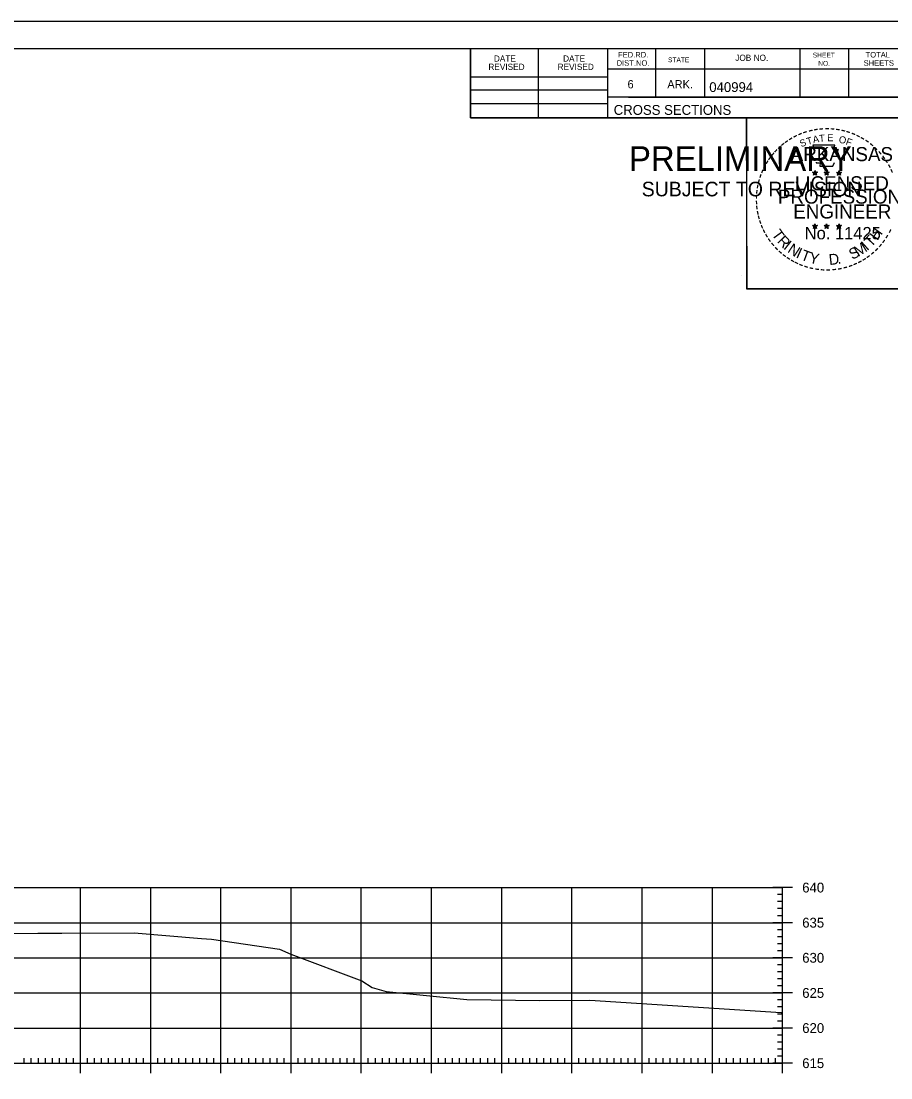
# Model space of a CAD drawing. Extents: x 1381471 to 1382703, y 370300 to 371487.
# Drawn here: x 1382168.2 to 1382292, y 371123.4 to 371273.8 of the extents above; entities that cross this region are included whole.
import ezdxf

# ---------------------------------------------------------------- set-up
doc = ezdxf.new("R2010")
doc.units = 0
doc.layers.add('Level 45', color=7, linetype='Continuous')

msp = doc.modelspace()

# ---------------------------------------------------------------- linework, layer by layer
at = {"layer": 'Level 45'}
for p, q in [((1381966.21, 371273.81), (1382299.55, 371273.81)), ((1381978.61, 371269.92), (1382294.79, 371269.92)), ((1382232.15, 371260.04), (1382232.15, 371269.92)), ((1382241.83, 371260.04), (1382241.83, 371269.92)), ((1382251.69, 371269.92), (1382251.69, 371260.04)), ((1382258.53, 371269.92), (1382258.53, 371262.98)), ((1382265.47, 371269.92), (1382265.47, 371262.98)), ((1382279.05, 371269.92), (1382279.05, 371262.98)), ((1382285.99, 371269.92), (1382285.99, 371262.98)), ((1382294.79, 371266.98), (1382251.69, 371266.98)), ((1382232.15, 371265.9), (1382251.69, 371265.9)), ((1382232.15, 371264.04), (1382251.69, 371264.04)), ((1382232.15, 371262.1), (1382251.69, 371262.1)), ((1382294.79, 371262.98), (1382251.69, 371262.98)), ((1382254.65, 371262.98), (1382294.79, 371262.98)), ((1382294.79, 371260.04), (1382232.15, 371260.04)), ((1382280.88, 371252.29), (1382281.23, 371252.18)), ((1382280.88, 371252.29), (1382281.13, 371252.25)), ((1382280.88, 371252.29), (1382281.12, 371252.17)), ((1382281.01, 371251.89), (1382281.23, 371252.18)), ((1382281.01, 371251.89), (1382281.14, 371252.13)), ((1382281.01, 371251.89), (1382281.23, 371252.1)), ((1382281.23, 371252.55), (1382281.19, 371252.3)), ((1382281.23, 371252.18), (1382281.23, 371252.55)), ((1382281.23, 371252.55), (1382281.28, 371252.3)), ((1382281.57, 371252.29), (1382281.23, 371252.18)), ((1382281.44, 371251.89), (1382281.23, 371252.18)), ((1382281.44, 371251.89), (1382281.23, 371252.1)), ((1382281.57, 371252.29), (1382281.29, 371252.24)), ((1382281.44, 371251.89), (1382281.3, 371252.18)), ((1382281.57, 371252.29), (1382281.37, 371252.19)), ((1382282.55, 371252.29), (1382282.9, 371252.18)), ((1382282.55, 371252.29), (1382282.8, 371252.25)), ((1382282.55, 371252.29), (1382282.79, 371252.17)), ((1382282.68, 371251.89), (1382282.9, 371252.18)), ((1382282.68, 371251.89), (1382282.81, 371252.13)), ((1382282.68, 371251.89), (1382282.9, 371252.1)), ((1382282.9, 371252.55), (1382282.86, 371252.3)), ((1382282.9, 371252.18), (1382282.9, 371252.55)), ((1382282.9, 371252.55), (1382282.95, 371252.3)), ((1382283.24, 371252.29), (1382282.9, 371252.18)), ((1382283.11, 371251.89), (1382282.9, 371252.18)), ((1382283.11, 371251.89), (1382282.9, 371252.1)), ((1382283.24, 371252.29), (1382282.96, 371252.24)), ((1382283.11, 371251.89), (1382282.97, 371252.18)), ((1382283.24, 371252.29), (1382283.04, 371252.19)), ((1382284.31, 371252.28), (1382284.66, 371252.17)), ((1382284.31, 371252.28), (1382284.57, 371252.24)), ((1382284.31, 371252.28), (1382284.55, 371252.16)), ((1382284.45, 371251.87), (1382284.66, 371252.17)), ((1382284.45, 371251.87), (1382284.57, 371252.12)), ((1382284.45, 371251.87), (1382284.66, 371252.09)), ((1382284.66, 371252.54), (1382284.62, 371252.28)), ((1382284.66, 371252.17), (1382284.66, 371252.54)), ((1382284.66, 371252.54), (1382284.71, 371252.29)), ((1382285.01, 371252.28), (1382284.66, 371252.17)), ((1382284.87, 371251.87), (1382284.66, 371252.17)), ((1382284.87, 371251.87), (1382284.66, 371252.09)), ((1382285.01, 371252.28), (1382284.72, 371252.23)), ((1382284.87, 371251.87), (1382284.74, 371252.16)), ((1382285.01, 371252.28), (1382284.8, 371252.18)), ((1382280.87, 371244.72), (1382281.22, 371244.61)), ((1382280.87, 371244.72), (1382281.13, 371244.68)), ((1382280.87, 371244.72), (1382281.11, 371244.6)), ((1382281.01, 371244.31), (1382281.22, 371244.61)), ((1382281.01, 371244.31), (1382281.13, 371244.56)), ((1382281.01, 371244.31), (1382281.22, 371244.53)), ((1382281.22, 371244.97), (1382281.18, 371244.72)), ((1382281.22, 371244.61), (1382281.22, 371244.97)), ((1382281.22, 371244.97), (1382281.27, 371244.72)), ((1382281.57, 371244.72), (1382281.22, 371244.61)), ((1382281.44, 371244.31), (1382281.22, 371244.61)), ((1382281.44, 371244.31), (1382281.22, 371244.53)), ((1382281.57, 371244.72), (1382281.28, 371244.67)), ((1382281.44, 371244.31), (1382281.3, 371244.6)), ((1382281.57, 371244.72), (1382281.37, 371244.62)), ((1382282.54, 371244.72), (1382282.89, 371244.61)), ((1382282.54, 371244.72), (1382282.8, 371244.68)), ((1382282.54, 371244.72), (1382282.78, 371244.6)), ((1382282.68, 371244.31), (1382282.89, 371244.61)), ((1382282.68, 371244.31), (1382282.8, 371244.56)), ((1382282.68, 371244.31), (1382282.89, 371244.53)), ((1382282.89, 371244.97), (1382282.85, 371244.72)), ((1382282.89, 371244.61), (1382282.89, 371244.97)), ((1382282.89, 371244.97), (1382282.94, 371244.72)), ((1382283.24, 371244.72), (1382282.89, 371244.61)), ((1382283.11, 371244.31), (1382282.89, 371244.61)), ((1382283.11, 371244.31), (1382282.89, 371244.53)), ((1382283.24, 371244.72), (1382282.95, 371244.67)), ((1382283.11, 371244.31), (1382282.97, 371244.6)), ((1382283.24, 371244.72), (1382283.04, 371244.62)), ((1382284.31, 371244.71), (1382284.66, 371244.6)), ((1382284.31, 371244.71), (1382284.56, 371244.67)), ((1382284.31, 371244.71), (1382284.55, 371244.59)), ((1382284.44, 371244.3), (1382284.66, 371244.6)), ((1382284.44, 371244.3), (1382284.57, 371244.55)), ((1382284.44, 371244.3), (1382284.66, 371244.52)), ((1382284.66, 371244.96), (1382284.62, 371244.71)), ((1382284.66, 371244.6), (1382284.66, 371244.96)), ((1382284.66, 371244.96), (1382284.71, 371244.71)), ((1382285.01, 371244.71), (1382284.66, 371244.6)), ((1382284.87, 371244.3), (1382284.66, 371244.6)), ((1382284.87, 371244.3), (1382284.66, 371244.52)), ((1382285.01, 371244.71), (1382284.72, 371244.66)), ((1382284.87, 371244.3), (1382284.74, 371244.59)), ((1382285.01, 371244.71), (1382284.8, 371244.61)), ((1382270.83, 371237.58), (1382270.83, 371237.58)), ((1381996.61, 371150.46), (1382276.61, 371150.46)), ((1382176.61, 371125.46), (1382176.61, 371150.46)), ((1382186.61, 371125.46), (1382186.61, 371150.46)), ((1382196.61, 371125.46), (1382196.61, 371150.46)), ((1382206.61, 371125.46), (1382206.61, 371150.46)), ((1382216.61, 371125.46), (1382216.61, 371150.46)), ((1382226.61, 371125.46), (1382226.61, 371150.46)), ((1382236.61, 371125.46), (1382236.61, 371150.46)), ((1382246.61, 371125.46), (1382246.61, 371150.46)), ((1382256.61, 371125.46), (1382256.61, 371150.46)), ((1382266.61, 371125.46), (1382266.61, 371150.46)), ((1382278.01, 371150.46), (1382275.21, 371150.46)), ((1382276.61, 371125.46), (1382276.61, 371150.46)), ((1382276.61, 371125.46), (1382276.61, 371150.46)), ((1382276.61, 371149.46), (1382275.91, 371149.46)), ((1382276.61, 371148.46), (1382275.91, 371148.46)), ((1382276.61, 371147.46), (1382275.91, 371147.46)), ((1382276.61, 371146.46), (1382275.91, 371146.46)), ((1381996.61, 371145.46), (1382276.61, 371145.46)), ((1382278.01, 371145.46), (1382275.21, 371145.46)), ((1382276.61, 371144.46), (1382275.91, 371144.46)), ((1382276.61, 371143.46), (1382275.91, 371143.46)), ((1382276.61, 371142.46), (1382275.91, 371142.46)), ((1382276.61, 371141.46), (1382275.91, 371141.46)), ((1381996.61, 371140.46), (1382276.61, 371140.46)), ((1382278.01, 371140.46), (1382275.21, 371140.46)), ((1382276.61, 371139.46), (1382275.91, 371139.46)), ((1382276.61, 371138.46), (1382275.91, 371138.46)), ((1382276.61, 371137.46), (1382275.91, 371137.46)), ((1381996.61, 371135.46), (1382276.61, 371135.46)), ((1382278.01, 371135.46), (1382275.21, 371135.46)), ((1382276.61, 371136.46), (1382275.91, 371136.46)), ((1382276.61, 371134.46), (1382275.91, 371134.46)), ((1382276.61, 371133.46), (1382275.91, 371133.46)), ((1382276.61, 371132.46), (1382275.91, 371132.46)), ((1382276.61, 371131.46), (1382275.91, 371131.46)), ((1381996.61, 371130.46), (1382276.61, 371130.46)), ((1382278.01, 371130.46), (1382275.21, 371130.46)), ((1382276.61, 371129.46), (1382275.91, 371129.46)), ((1382276.61, 371128.46), (1382275.91, 371128.46)), ((1382176.61, 371124.06), (1382176.61, 371126.86)), ((1382186.61, 371124.06), (1382186.61, 371126.86)), ((1382196.61, 371124.06), (1382196.61, 371126.86)), ((1382206.61, 371124.06), (1382206.61, 371126.86)), ((1382216.61, 371124.06), (1382216.61, 371126.86)), ((1382226.61, 371124.06), (1382226.61, 371126.86)), ((1382236.61, 371124.06), (1382236.61, 371126.86)), ((1382246.61, 371124.06), (1382246.61, 371126.86)), ((1382256.61, 371124.06), (1382256.61, 371126.86)), ((1382266.61, 371124.06), (1382266.61, 371126.86)), ((1382276.61, 371127.46), (1382275.91, 371127.46)), ((1382276.61, 371126.46), (1382275.91, 371126.46)), ((1382276.61, 371124.06), (1382276.61, 371126.86)), ((1381996.61, 371125.46), (1382276.61, 371125.46)), ((1381996.61, 371125.46), (1382276.61, 371125.46)), ((1382168.61, 371125.46), (1382168.61, 371126.16)), ((1382169.61, 371125.46), (1382169.61, 371126.16)), ((1382170.61, 371125.46), (1382170.61, 371126.16)), ((1382171.61, 371125.46), (1382171.61, 371126.16)), ((1382172.61, 371125.46), (1382172.61, 371126.16)), ((1382173.61, 371125.46), (1382173.61, 371126.16)), ((1382174.61, 371125.46), (1382174.61, 371126.16)), ((1382175.61, 371125.46), (1382175.61, 371126.16)), ((1382177.61, 371125.46), (1382177.61, 371126.16)), ((1382178.61, 371125.46), (1382178.61, 371126.16)), ((1382179.61, 371125.46), (1382179.61, 371126.16)), ((1382180.61, 371125.46), (1382180.61, 371126.16)), ((1382181.61, 371125.46), (1382181.61, 371126.16)), ((1382182.61, 371125.46), (1382182.61, 371126.16)), ((1382183.61, 371125.46), (1382183.61, 371126.16)), ((1382184.61, 371125.46), (1382184.61, 371126.16)), ((1382185.61, 371125.46), (1382185.61, 371126.16)), ((1382187.61, 371125.46), (1382187.61, 371126.16)), ((1382188.61, 371125.46), (1382188.61, 371126.16)), ((1382189.61, 371125.46), (1382189.61, 371126.16)), ((1382190.61, 371125.46), (1382190.61, 371126.16)), ((1382191.61, 371125.46), (1382191.61, 371126.16)), ((1382192.61, 371125.46), (1382192.61, 371126.16)), ((1382193.61, 371125.46), (1382193.61, 371126.16)), ((1382194.61, 371125.46), (1382194.61, 371126.16)), ((1382195.61, 371125.46), (1382195.61, 371126.16)), ((1382197.61, 371125.46), (1382197.61, 371126.16)), ((1382198.61, 371125.46), (1382198.61, 371126.16)), ((1382199.61, 371125.46), (1382199.61, 371126.16)), ((1382200.61, 371125.46), (1382200.61, 371126.16)), ((1382201.61, 371125.46), (1382201.61, 371126.16)), ((1382202.61, 371125.46), (1382202.61, 371126.16)), ((1382203.61, 371125.46), (1382203.61, 371126.16)), ((1382204.61, 371125.46), (1382204.61, 371126.16)), ((1382205.61, 371125.46), (1382205.61, 371126.16)), ((1382207.61, 371125.46), (1382207.61, 371126.16)), ((1382208.61, 371125.46), (1382208.61, 371126.16)), ((1382209.61, 371125.46), (1382209.61, 371126.16)), ((1382210.61, 371125.46), (1382210.61, 371126.16)), ((1382211.61, 371125.46), (1382211.61, 371126.16)), ((1382212.61, 371125.46), (1382212.61, 371126.16)), ((1382213.61, 371125.46), (1382213.61, 371126.16)), ((1382214.61, 371125.46), (1382214.61, 371126.16)), ((1382215.61, 371125.46), (1382215.61, 371126.16)), ((1382217.61, 371125.46), (1382217.61, 371126.16)), ((1382218.61, 371125.46), (1382218.61, 371126.16)), ((1382219.61, 371125.46), (1382219.61, 371126.16)), ((1382220.61, 371125.46), (1382220.61, 371126.16)), ((1382221.61, 371125.46), (1382221.61, 371126.16)), ((1382222.61, 371125.46), (1382222.61, 371126.16)), ((1382223.61, 371125.46), (1382223.61, 371126.16)), ((1382224.61, 371125.46), (1382224.61, 371126.16)), ((1382225.61, 371125.46), (1382225.61, 371126.16)), ((1382227.61, 371125.46), (1382227.61, 371126.16)), ((1382228.61, 371125.46), (1382228.61, 371126.16)), ((1382229.61, 371125.46), (1382229.61, 371126.16)), ((1382230.61, 371125.46), (1382230.61, 371126.16)), ((1382231.61, 371125.46), (1382231.61, 371126.16)), ((1382232.61, 371125.46), (1382232.61, 371126.16)), ((1382233.61, 371125.46), (1382233.61, 371126.16)), ((1382234.61, 371125.46), (1382234.61, 371126.16)), ((1382235.61, 371125.46), (1382235.61, 371126.16)), ((1382237.61, 371125.46), (1382237.61, 371126.16)), ((1382238.61, 371125.46), (1382238.61, 371126.16)), ((1382239.61, 371125.46), (1382239.61, 371126.16)), ((1382240.61, 371125.46), (1382240.61, 371126.16)), ((1382241.61, 371125.46), (1382241.61, 371126.16)), ((1382242.61, 371125.46), (1382242.61, 371126.16)), ((1382243.61, 371125.46), (1382243.61, 371126.16)), ((1382244.61, 371125.46), (1382244.61, 371126.16)), ((1382245.61, 371125.46), (1382245.61, 371126.16)), ((1382247.61, 371125.46), (1382247.61, 371126.16)), ((1382248.61, 371125.46), (1382248.61, 371126.16)), ((1382249.61, 371125.46), (1382249.61, 371126.16)), ((1382250.61, 371125.46), (1382250.61, 371126.16)), ((1382251.61, 371125.46), (1382251.61, 371126.16)), ((1382252.61, 371125.46), (1382252.61, 371126.16)), ((1382253.61, 371125.46), (1382253.61, 371126.16)), ((1382254.61, 371125.46), (1382254.61, 371126.16)), ((1382255.61, 371125.46), (1382255.61, 371126.16)), ((1382257.61, 371125.46), (1382257.61, 371126.16)), ((1382258.61, 371125.46), (1382258.61, 371126.16)), ((1382259.61, 371125.46), (1382259.61, 371126.16)), ((1382260.61, 371125.46), (1382260.61, 371126.16)), ((1382261.61, 371125.46), (1382261.61, 371126.16)), ((1382262.61, 371125.46), (1382262.61, 371126.16)), ((1382263.61, 371125.46), (1382263.61, 371126.16)), ((1382264.61, 371125.46), (1382264.61, 371126.16)), ((1382265.61, 371125.46), (1382265.61, 371126.16)), ((1382267.61, 371125.46), (1382267.61, 371126.16)), ((1382268.61, 371125.46), (1382268.61, 371126.16)), ((1382269.61, 371125.46), (1382269.61, 371126.16)), ((1382270.61, 371125.46), (1382270.61, 371126.16)), ((1382271.61, 371125.46), (1382271.61, 371126.16)), ((1382272.61, 371125.46), (1382272.61, 371126.16)), ((1382273.61, 371125.46), (1382273.61, 371126.16)), ((1382274.61, 371125.46), (1382274.61, 371126.16)), ((1382278.01, 371125.46), (1382275.21, 371125.46)), ((1382275.61, 371125.46), (1382275.61, 371126.16))]:
    msp.add_line(p, q, dxfattribs=at)
for points in [[(1381966.21, 371273.81), (1382299.55, 371273.81), (1382299.55, 371060.48), (1381966.21, 371060.48)], [(1382212.53, 371269.92), (1382232.15, 371269.92), (1382232.15, 371260.04), (1382248.27, 371260.04), (1382271.46, 371260.04), (1382271.46, 371235.71), (1382294.79, 371235.71), (1382294.79, 371064.46), (1381978.61, 371064.46), (1381978.61, 371269.92)], [(1382271.46, 371260.04), (1382294.67, 371260.04), (1382294.79, 371235.71), (1382271.59, 371235.71)]]:
    msp.add_lwpolyline(points, close=True, dxfattribs=at)
for points in [[(1382280.92, 371256.17), (1382281.19, 371255.34)], [(1382284.43, 371255.25), (1382284.57, 371255.53), (1382283.89, 371255.51), (1382284.04, 371256.17), (1382280.92, 371256.17)], [(1382281.41, 371253.75), (1382281.41, 371253.66), (1382281.97, 371253.64), (1382281.92, 371253.17), (1382283.79, 371253.17), (1382283.99, 371253.71)], [(1382281.23, 371252.55), (1382281.44, 371251.89), (1382280.88, 371252.29), (1382281.57, 371252.29), (1382281.01, 371251.89), (1382281.23, 371252.55)], [(1382282.9, 371252.55), (1382283.11, 371251.89), (1382282.55, 371252.29), (1382283.24, 371252.29), (1382282.68, 371251.89), (1382282.9, 371252.55)], [(1382284.66, 371252.54), (1382284.87, 371251.87), (1382284.31, 371252.28), (1382285.01, 371252.28), (1382284.45, 371251.87), (1382284.66, 371252.54)], [(1382281.22, 371244.97), (1382281.44, 371244.31), (1382280.87, 371244.72), (1382281.57, 371244.72), (1382281.01, 371244.31), (1382281.22, 371244.97)], [(1382282.89, 371244.97), (1382283.11, 371244.31), (1382282.54, 371244.72), (1382283.24, 371244.72), (1382282.68, 371244.31), (1382282.89, 371244.97)], [(1382284.66, 371244.96), (1382284.87, 371244.3), (1382284.31, 371244.71), (1382285.01, 371244.71), (1382284.44, 371244.3), (1382284.66, 371244.96)], [(1382162.08, 371143.87), (1382170.53, 371143.98), (1382173.95, 371143.98), (1382184.28, 371144.03), (1382193.86, 371143.21), (1382195.28, 371143.13), (1382204.97, 371141.67), (1382206.57, 371140.98), (1382216.67, 371137.17), (1382218.15, 371136.24), (1382220.17, 371135.66), (1382231.64, 371134.54), (1382242.04, 371134.4), (1382249.15, 371134.45), (1382276.42, 371132.68), (1382276.61, 371132.67)]]:
    msp.add_lwpolyline(points, dxfattribs=at)
for centre, radius in [((1382281.23, 371252.18), 0.172), ((1382281.23, 371252.18), 0.145), ((1382281.23, 371252.18), 0.116), ((1382281.23, 371252.18), 0.0991), ((1382281.23, 371252.18), 0.0747), ((1382281.23, 371252.18), 0.0495), ((1382281.23, 371252.18), 0.0296), ((1382282.9, 371252.18), 0.172), ((1382282.9, 371252.18), 0.145), ((1382282.9, 371252.18), 0.116), ((1382282.9, 371252.18), 0.0991), ((1382282.9, 371252.18), 0.0747), ((1382282.9, 371252.18), 0.0495), ((1382282.9, 371252.18), 0.0296), ((1382284.66, 371252.17), 0.172), ((1382284.66, 371252.17), 0.145), ((1382284.66, 371252.17), 0.116), ((1382284.66, 371252.17), 0.0991), ((1382284.66, 371252.17), 0.0747), ((1382284.66, 371252.17), 0.0495), ((1382284.66, 371252.17), 0.0296), ((1382281.22, 371244.61), 0.172), ((1382281.22, 371244.61), 0.145), ((1382281.22, 371244.61), 0.116), ((1382281.22, 371244.61), 0.0991), ((1382281.22, 371244.61), 0.0747), ((1382281.22, 371244.61), 0.0495), ((1382281.22, 371244.61), 0.0296), ((1382282.89, 371244.61), 0.172), ((1382282.89, 371244.61), 0.145), ((1382282.89, 371244.61), 0.116), ((1382282.89, 371244.61), 0.0991), ((1382282.89, 371244.61), 0.0747), ((1382282.89, 371244.61), 0.0495), ((1382282.89, 371244.61), 0.0296), ((1382284.66, 371244.6), 0.172), ((1382284.66, 371244.6), 0.145), ((1382284.66, 371244.6), 0.116), ((1382284.66, 371244.6), 0.0991), ((1382284.66, 371244.6), 0.0747), ((1382284.66, 371244.6), 0.0495), ((1382284.66, 371244.6), 0.0296)]:
    msp.add_circle(centre, radius, dxfattribs=at)

# ---------------------------------------------------------------- texts
for s, height, rotation, p in [('FED.RD.', 0.782, 360, (1382253.17, 371268.64)), ('SHEET', 0.684, 360, (1382280.91, 371268.64)), ('TOTAL', 0.782, 360, (1382288.43, 371268.64)), ('REVISED', 0.879, 360, (1382234.71, 371266.87)), ('DATE', 0.879, 360, (1382235.49, 371268.05)), ('REVISED', 0.879, 360, (1382244.57, 371266.87)), ('DATE', 0.879, 360, (1382245.35, 371268.05)), ('DIST.NO.', 0.782, 360, (1382252.97, 371267.46)), ('STATE', 0.684, 360, (1382260.29, 371267.96)), ('JOB NO.', 0.879, 360, (1382269.87, 371268.16)), ('NO.', 0.684, 360, (1382281.69, 371267.46)), ('SHEETS', 0.782, 360, (1382288.15, 371267.46)), ('6', 1.17, 360, (1382254.53, 371264.24)), ('ARK.', 1.172, 360, (1382260.19, 371264.24)), ('040994', 1.4, 360, (1382266.17, 371263.72)), ('CROSS SECTIONS', 1.4, 360, (1382252.56, 371260.47)), ('-', 1.6, 34.0636, (1382277.8, 371256.34)), ('-', 1.6, 28.7918, (1382278.4, 371256.71)), ('-', 1.6, 24.3072, (1382279.03, 371257.03)), ('-', 1.6, 19.1761, (1382279.67, 371257.3)), ('T', 1, 16.4036, (1382280.19, 371256.18)), ('-', 1.6, 13.6301, (1382280.42, 371257.54)), ('A', 1, 11.2132, (1382281.01, 371256.43)), ('-', 1.6, 10.2193, (1382281.1, 371257.7)), ('T', 1, 6.0228, (1382281.86, 371256.6)), ('-', 1.6, 5.8968, (1382281.82, 371257.81)), ('-', 1.6, 0.1862, (1382282.6, 371257.88)), ('E', 1, 0.8323, (1382282.97, 371256.71)), ('-', 1.6, 357.743, (1382283.32, 371257.87)), ('-', 1.6, 352.1617, (1382284.06, 371257.81)), ('O', 1, 350.4515, (1382284.57, 371256.5)), ('-', 1.6, 347.2049, (1382284.78, 371257.7)), ('-', 1.6, 342.3362, (1382285.42, 371257.55)), ('-', 1.6, 337.8551, (1382286.15, 371257.32)), ('-', 1.6, 334.1211, (1382286.78, 371257.05)), ('-', 1.6, 329.6409, (1382287.36, 371256.77)), ('PRELIMINARY', 3.5, 360, (1382254.74, 371252.5)), ('-', 1.6, 42.9622, (1382276.32, 371255.15)), ('-', 1.6, 38.9507, (1382276.75, 371255.57)), ('-', 1.6, 36.2317, (1382277.23, 371255.95)), ('ARKANSAS', 2, 360, (1382277.77, 371253.88)), ('S', 1, 21.594, (1382279.27, 371255.85)), ('F', 1, 340.0707, (1382285.53, 371256.27)), ('-', 1.6, 325.8627, (1382288.01, 371256.41)), ('-', 1.6, 320.5297, (1382288.62, 371255.98)), ('-', 1.6, 315.5786, (1382289.21, 371255.49)), ('DWB', 0.01, 360, (1382255.49, 371254.35)), ('-', 1.6, 54.2325, (1382275.05, 371253.62)), ('-', 1.6, 50.6142, (1382275.47, 371254.19)), ('-', 1.6, 48.423, (1382275.87, 371254.67)), ('-', 1.6, 309.8797, (1382289.78, 371254.94)), ('-', 1.6, 306.6522, (1382290.31, 371254.34)), ('-', 1.6, 62.8713, (1382274.41, 371252.48)), ('-', 1.6, 58.0706, (1382274.73, 371253.09)), ('-', 1.4, 303.6753, (1382290.79, 371253.77)), ('-', 1.6, 299.6684, (1382291.11, 371253.17)), ('-', 1.6, 294.6628, (1382291.44, 371252.55)), ('-', 1.6, 75.461, (1382273.74, 371250.53)), ('-', 1.6, 72.3945, (1382273.94, 371251.24)), ('-', 1.6, 67.7743, (1382274.16, 371251.87)), ('LICENSED', 2, 360, (1382278.37, 371249.73)), ('DWB', 0.01, 360, (1382281.21, 371252.18)), ('DWB', 0.01, 360, (1382282.88, 371252.18)), ('DWB', 0.01, 360, (1382284.65, 371252.17)), ('SUBJECT TO REVISION', 2.0751, 360, (1382256.55, 371248.87)), ('-', 1.6, 85.1863, (1382273.53, 371249.12)), ('-', 1.6, 81.2013, (1382273.61, 371249.81)), ('PROFESSIONAL', 2, 360, (1382275.95, 371247.83)), ('-', 1.6, 94.1959, (1382273.54, 371247.7)), ('-', 1.6, 89.0622, (1382273.51, 371248.42)), ('-', 1.6, 98.9479, (1382273.61, 371247.03)), ('-', 1.6, 101.7149, (1382273.75, 371246.3)), ('ENGINEER', 2, 360, (1382278.13, 371245.71)), ('-', 1.6, 105.4578, (1382273.91, 371245.7)), ('-', 1.6, 109.0874, (1382274.13, 371245.07)), ('-', 1.6, 114.0643, (1382274.38, 371244.47)), ('-', 1.6, 115.7289, (1382274.68, 371243.86)), ('T', 1.54, 306.0406, (1382274.98, 371243.45)), ('No. 11425', 1.757, 360, (1382279.76, 371242.75)), ('DWB', 0.01, 360, (1382281.21, 371244.6)), ('DWB', 0.01, 360, (1382282.88, 371244.6)), ('DWB', 0.01, 360, (1382284.65, 371244.59)), ('H', 1.54, 54.6088, (1382290.1, 371242.48)), ('-', 1.6, 244.6197, (1382291.52, 371244.51)), ('-', 1.6, 120.4471, (1382275.04, 371243.27)), ('-', 1.6, 125.8934, (1382275.44, 371242.71)), ('-', 1.6, 130.7181, (1382275.91, 371242.16)), ('R', 1.54, 314.005, (1382275.75, 371242.4)), ('I', 1.54, 321.9694, (1382276.65, 371241.47)), ('M', 1.54, 32.6563, (1382287.37, 371240.22)), ('I', 1.54, 42.1136, (1382288.65, 371241.06)), ('T', 1.54, 46.6444, (1382289.21, 371241.54)), ('-', 1.6, 233.8452, (1382290.72, 371243.11)), ('-', 1.6, 239.0712, (1382291.12, 371243.76)), ('-', 1.6, 134.2238, (1382276.42, 371241.61)), ('-', 1.6, 138.9338, (1382276.95, 371241.15)), ('N', 1.54, 326.5002, (1382277.21, 371241)), ('I', 1.54, 335.3603, (1382278.42, 371240.21)), ('T', 1.54, 339.8912, (1382279.08, 371239.88)), ('Y', 1.54, 347.8556, (1382280.3, 371239.44)), ('D', 1.54, 6.3969, (1382283.28, 371239.08)), ('S', 1.54, 26.9312, (1382286.53, 371239.81)), ('-', 1.6, 221.0851, (1382289.29, 371241.47)), ('-', 1.6, 225.7653, (1382289.81, 371241.98)), ('-', 1.6, 231.2538, (1382290.29, 371242.54)), ('-', 1.6, 144.6463, (1382277.5, 371240.74)), ('-', 1.6, 148.0898, (1382278.07, 371240.37)), ('-', 1.6, 151.5704, (1382278.64, 371240.05)), ('-', 1.6, 154.6002, (1382279.17, 371239.8)), ('-', 1.6, 158.5612, (1382279.79, 371239.54)), ('.', 1.54, 13.7642, (1382284.48, 371239.21)), ('-', 1.6, 204.2516, (1382287.03, 371239.95)), ('-', 1.6, 207.3568, (1382287.65, 371240.26)), ('-', 1.6, 212.2491, (1382288.21, 371240.61)), ('-', 1.6, 215.7363, (1382288.74, 371241)), ('-', 1.6, 162.7983, (1382280.48, 371239.33)), ('-', 1.6, 167.5555, (1382281.19, 371239.17)), ('-', 1.6, 173.1155, (1382281.96, 371239.06)), ('-', 1.6, 176.5183, (1382282.71, 371239)), ('-', 1.6, 181.5918, (1382283.46, 371239.02)), ('-', 1.6, 185.8167, (1382284.27, 371239.1)), ('-', 1.6, 191.2858, (1382285, 371239.23)), ('-', 1.6, 195.4743, (1382285.73, 371239.43)), ('-', 1.6, 200.7184, (1382286.41, 371239.67))]:
    msp.add_text(s, height=height, rotation=rotation, dxfattribs=at).set_placement(p)
for s, p in [('640', (1382279.41, 371149.76)), ('635', (1382279.41, 371144.76)), ('630', (1382279.41, 371139.76)), ('625', (1382279.41, 371134.76)), ('620', (1382279.41, 371129.76)), ('615', (1382279.41, 371124.76))]:
    msp.add_text(s, height=1.4, dxfattribs=at).set_placement(p)

doc.saveas('drawing.dxf')
